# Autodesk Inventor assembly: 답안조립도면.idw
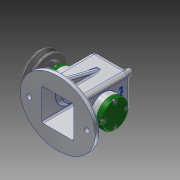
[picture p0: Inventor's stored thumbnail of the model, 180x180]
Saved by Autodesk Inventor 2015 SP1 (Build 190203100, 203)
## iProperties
Created: 2017-07
Part Number: 답안조립도면.idw
Document SubType Name: Assembly
Designer: C04
Author: C04
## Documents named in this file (16)
- C:\Users\C04\Desktop\470707V1009\답안조립도면.idw.iam
- C:\Users\C04\Desktop\470707V1009\본체.ipt
- C:\Users\C04\Desktop\470707V1009\뒤커버.ipt
- C:\Users\C04\Desktop\470707V1009\앞커버.ipt
- C:\Users\C04\Desktop\470707V1009\베어링 12 x 32 x 10.ipt
- C:\Users\C04\Desktop\470707V1009\오일실 12 25 7.ipt
- C:\Users\C04\Desktop\470707V1009\편심축.ipt
- C:\Users\C04\Desktop\470707V1009\링크.ipt
- C:\Users\C04\Desktop\470707V1009\고정핀 1.2 x  8.ipt
- C:\Users\C04\Desktop\470707V1009\핀 5 x 18.ipt
- C:\Users\C04\Desktop\470707V1009\슬라이드.ipt
- C:\Users\C04\Desktop\470707V1009\부시.ipt
- C:\Users\C04\Desktop\470707V1009\V벨트풀리.ipt
- C:\Users\C04\Desktop\470707V1009\키 4 x 4 x 10.ipt
- C:\Users\C04\Desktop\470707V1009\볼트 M4 x 12.ipt
- C:\Users\C04\Desktop\470707V1009\멈춤나사 M3x8.ipt
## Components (3 placed, 3 different names)
1. 고정핀 1.2 x  8:1
2. 핀 5 x 18:1
3. V벨트풀리:1 — 각도:1, 각도:2
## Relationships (2: Angle 2)
- 각도:1 [Angle]: V벨트풀리:1
- 각도:2 [Angle]: V벨트풀리:1
